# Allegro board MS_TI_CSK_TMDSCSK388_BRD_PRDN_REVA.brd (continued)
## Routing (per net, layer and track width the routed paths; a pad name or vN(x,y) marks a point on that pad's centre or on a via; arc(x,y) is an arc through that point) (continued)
DM388_SPI[0]_SCLK: length 45.9
  L03_SIG1 w0.119: v1(69.57,23.95) 69.89,23.64 71.66,23.64 71.81,23.5 72.96,23.5 73.14,23.31 73.49,23.31 73.88,23.7 v1(75.85,23.7)
  BOTTOM w0.102: R129.2 51.72,8.22 52.74,7.21
  BOTTOM w0.14: 52.74,7.21 53.58,6.37 54.6,6.37 55.2,5.77 63.74,5.77 69.91,11.95 70.17,11.95 75.02,16.79 75.02,18.07 75.85,18.89 75.85,23.19 75.85,23.19 v1(75.85,23.7) ; v1(69.57,23.95) 69.5,23.95 69.27,23.73 J3.68
DM388_TCLK: length 43.6
  TOP w0.102: v1(48.44,10.31) 48.41,10.34 U7.T29
  L03_SIG1 w0.102: v1(48.44,10.31) 48.01,10.74 48.01,13.87 46.94,14.94 46.17,14.94 45.35,15.76 45.35,17.6 45.36,17.6 45.36,17.63 45.62,17.9 47.53,17.9 47.63,18 47.63,19.41 48.04,19.81 48.04,20.25 48.31,20.52 48.31,20.83 48.56,21.08 49.04,21.08 49.43,20.7 49.78,20.7 50.14,21.06 50.14,23.72 51.02,24.59 51.31,24.59 52.25,25.53 52.25,25.99 52.86,26.59
  L03_SIG1 w0.119: v1(53.2,29.95) 53.2,28.87 53.61,28.46 53.61,27.91 53.24,27.54 53.24,26.98 52.86,26.59
  BOTTOM w0.14: v1(53.2,29.95) 53.2,29.94 53.29,29.85 54.7,29.85 54.87,29.67 55.74,29.67 56.32,30.25 57.48,30.25 58.17,30.94 59.34,30.94 59.47,30.81 66.43,30.81 67.35,31.73 J3.38
DM388_TDI: length 38.8
  TOP w0.102: U7.N28 49.11,10.84 v1(49,10.95)
  L03_SIG1 w0.102: 53.79,26.59 53.79,25.97 53.55,25.73 53.44,25.73 52.91,25.2 52.91,24.8 52.29,24.18 51.28,24.18 50.58,23.48 50.58,20.88 49.6,19.91 49.6,19.82 49.08,19.3 48.74,19.3 48.04,18.59 48.04,15.2 48.38,14.86 49.76,14.86 49.97,14.65 49.97,13.96 49.53,13.52 49.53,13.21 49.59,13.15 49.59,11.53 v1(49,10.95)
  L03_SIG1 w0.119: v1(54.21,27.73) 53.79,27.3 53.79,26.59
  BOTTOM w0.14: J3.44 64.01,30.23 63.81,30.42 59.64,30.42 59.13,29.91 56.76,29.91 55.7,28.85 54.75,28.85 54.59,29.01 54.05,29.01 53.87,28.83 53.87,28.07 v1(54.21,27.73)
DM388_TDO: length 68.3
  L06_SIG2 w0.119: v1(76.74,30.99) 77.12,30.61 77.12,30.03 76.87,29.79 76.11,29.79 75.62,30.27 v1(70.47,30.27)
  BOTTOM w0.102: R133.2 47.71,10.41 48.49,9.63 48.49,7.85 48.55,7.79
  BOTTOM w0.14: v1(76.74,30.99) 77.45,30.28 77.45,23.04 77.16,22.75 77.16,18.35 76.33,17.53 76.33,12.75 67.15,3.57 56.66,3.57 56.42,3.33 50.7,3.33 49.5,4.53 49.5,6.32 48.76,7.06 48.76,7.58 48.55,7.79 ; J3.46 68.48,29.73 68.49,29.74 69.93,29.74 v1(70.47,30.27)
DM388_TMS: length 58
  TOP w0.102: U7.T31 49.46,7.86 49.46,7.79
  TOP w0.14: v1(49.46,7.42) 49.46,7.79
  L06_SIG2 w0.119: v1(75.62,31.95) 75.18,31.95 75.04,32.1 69.68,32.1 v1(69.37,32.41)
  BOTTOM w0.14: J3.36 68.74,32.23 68.92,32.41 v1(69.37,32.41) ; v1(49.46,7.42) 51.71,7.42 53.1,6.03 54.46,6.03 55.06,5.43 64.13,5.43 70.3,11.6 70.32,11.6 75.37,16.65 75.37,17.93 76.19,18.75 76.19,23.15 76.27,23.23 76.27,27.75 75.62,28.4 v1(75.62,31.95)
DM388_TPS_SLEEP: length 49.9
  TOP w0.102: v1(49.59,21.08) 49.59,21.06 49.48,20.95 U7.N9 ; U1.F1 33.36,48.06 33.36,47.3 33.18,47.12 v1(33.18,46.74)
  L06_SIG2 w0.102: 56.88,26.59 56.88,26.37 53.69,23.18 52.62,23.18 51.86,22.42 51.86,21.66 51.64,21.44 49.95,21.44 v1(49.59,21.08) ; 33.61,46.3 v1(33.18,46.74)
  L06_SIG2 w0.119: 56.88,26.59 56.88,28.57 56.44,29.01 56.44,31.24 55.63,32.06 55.63,32.61 55.23,33.02 55.23,33.56 55.06,33.72 55.06,33.78 54.29,34.55 54.29,35.32 53.11,36.5 50.82,36.5 50.2,37.13 50.2,40.32 49.91,40.61 49.26,40.61 47.76,42.11 45.93,42.11 44.05,43.99 35.92,43.99 33.61,46.3
DM388_TRSTN: length 39.7
  TOP w0.102: U7.U24 47.15,12.84 47,12.99 47,12.99 v1(46.98,13)
  TOP w0.14: v1(70.38,31.23) 70.87,31.23 70.98,31.34 R120.1
  L06_SIG2 w0.102: v1(46.98,13) 47.37,13.39 47.37,14.66 47.83,15.11 47.83,15.53 48.69,16.38 49.69,16.38 50.19,16.89 54.73,16.89 57.37,19.53
  L06_SIG2 w0.119: v1(70.38,31.23) 69.91,30.76 66.6,30.76 66.3,30.46 63.11,30.46 60.48,27.82 60.48,25.02 59.3,23.84 59.3,21.24 57.59,19.53 57.37,19.53
  BOTTOM w0.14: J3.42 68.48,30.73 68.54,30.79 69.94,30.79 v1(70.38,31.23)
DM388_UART0_CTSN: length 21.2
  TOP w0.102: 57.31,10.29 56.67,10.29 56.44,10.06 56.44,9.34 56.16,9.06 54.76,9.06 U7.D30
  TOP w0.14: 57.31,10.29 59.74,10.29 60.32,10.86 60.32,11.17 60.82,11.67 61.32,11.67 61.44,11.79 65.54,11.79 v1(66.58,12.83)
  BOTTOM w0.14: J5.39 64.72,16.77 64.72,16.77 65.08,16.77 65.09,16.77 65.81,16.77 66.58,16 v1(66.58,12.83)
DM388_UART0_RTSN: length 24.2
  TOP w0.102: 57.31,8 56.71,8 55.94,8.76 54.55,8.76 U7.D31
  TOP w0.14: v1(67.31,12.83) 67.34,12.8 67.34,12.29 66.21,11.16 66.21,9.95 65.71,9.45 64.72,9.45 62.67,7.39 59.6,7.39 59.31,7.68 58.19,7.68 57.87,8 57.31,8
  BOTTOM w0.14: J5.37 64.93,17.27 65.18,17.01 65.91,17.01 66.87,16.05 66.87,13.27 v1(67.31,12.83)
DM388_UART0_RXD: length 61.4
  TOP w0.102: U7.J26 51.48,11.94 50.97,12.44 v1(50.96,12.44)
  L03_SIG1 w0.102: v1(50.96,12.44) 51.27,12.14 51.28,12.14 51.43,11.98 51.43,10.31 50.93,9.81 48.42,9.81 46.73,8.12 46.73,7.79
  L03_SIG1 w0.119: v1(74.48,21.79) 73.43,21.79 72.7,21.06 72.7,18.6 75.82,15.49 75.82,11.07 66.79,2.04 50.94,2.04 50.92,2.05 50.08,2.05 49.65,2.48 49.65,3.18 46.92,5.92 46.92,7.04 46.73,7.22 46.73,7.79
  BOTTOM w0.14: J3.71 73.54,22.73 v1(74.48,21.79)
DM388_UART0_TXD: length 35.8
  TOP w0.14: R80.1 58.56,8.89 58.7,8.74 v1(58.7,8.29)
  L06_SIG2 w0.119: v1(74.15,22.71) 72.57,21.14 69.91,21.14 69.83,21.05 69.8,21.05 67.7,18.95 67.7,17.33 67.83,17.21 71.32,13.72 71.32,10.42 68,7.1 59.9,7.1 v1(58.7,8.29)
  BOTTOM w0.14: J3.69 73.63,23.23 v1(74.15,22.71)
DM388_UART1_RXD: length 41
  TOP w0.102: U7.N26 49.22,11.84 49.12,11.74 49.12,11.69 49.02,11.59 v1(48.98,11.59)
  L03_SIG1 w0.102: 53.25,26.59 52.71,26.05 52.71,24.88 52.21,24.38 51.19,24.38 50.37,23.56 50.37,20.98 49.4,20.01 49.4,19.91 48.99,19.5 48.23,19.5 47.83,19.1 47.83,14.99 48.5,14.32 49.01,14.32 49.37,13.96 49.37,13.65 49.32,13.61 49.32,13.02 49.37,12.97 49.37,12.39 49.37,12.39 49.37,12.08 49.36,12.06 49.36,11.98 v1(48.98,11.59)
  L03_SIG1 w0.119: 53.25,26.59 53.52,26.86 53.52,27.5 53.83,27.81 53.83,30.02 v1(53.24,30.61)
  BOTTOM w0.14: v1(53.24,30.61) 53.56,30.29 54.63,30.29 54.87,30.53 55.7,30.53 56.9,31.73 58.73,31.73 59.14,32.13 61.57,32.13 64.17,34.73 J3.28
DM388_UART1_TXD: length 53.9
  L06_SIG2 w0.119: v1(75.38,36.35) 74.94,36.35 74.9,36.31 73.97,36.31 73.73,36.55 73.73,36.9 73.49,37.14 73.14,37.14 72.35,36.35 67.98,36.35 67.69,36.06 67.69,35.62 67.42,35.35 v1(66.86,35.35)
  BOTTOM w0.14: J3.26 67.01,35.23 66.89,35.35 v1(66.86,35.35) ; R134.1 64.41,6.99 69.77,12.35 70.09,12.35 74.68,16.94 74.68,18.21 75.51,19.04 75.51,23.05 75.42,23.13 75.42,24.1 75.95,24.63 75.95,27.71 75.38,28.29 75.38,30.99 75.21,31.16 75.21,32.86 75.7,33.34 75.7,36.03 v1(75.38,36.35)
DM388_UART2_CTSN: length 8.3
  TOP w0.14: U2.7 v1(49.8,42.44) ; U4.3 v1(54.11,37.34)
  L03_SIG1 w0.119: v1(54.11,37.34) 53.11,38.34 53.11,39.14 v1(49.8,42.44)
DM388_UART2_RTSN: length 12.1
  TOP w0.14: U2.5 48.99,44 48.39,43.41 v1(48.39,42.83) ; U4.6 53.99,38.84 53.99,38.84 v1(54.46,38.84)
  L06_SIG2 w0.119: v1(48.39,42.83) 48.83,42.83 49.03,43.03 49.82,43.03 50.89,41.96 52.33,41.96 54.77,39.52 54.77,39.15 v1(54.46,38.84)
DM388_UART2_RXD: length 91.8
  TOP w0.102: U7.L22 v1(50.48,13.41)
  TOP w0.14: U2.6 49.2,43.5 48.9,43.2 48.9,42.19 v1(49.1,41.99)
  L03_SIG1 w0.102: 57.31,12.07 57.28,12.07 57.26,12.09 54.11,12.09 53.12,13.08 51.24,13.08 50.91,13.41 v1(50.48,13.41)
  L03_SIG1 w0.119: v1(49.1,41.99) 49.1,42.33 49.63,42.86 50.44,42.86 51.55,41.75 54.5,41.75 56.97,44.21 61.31,44.21 61.75,44.65 65.38,44.65 v1(67.01,43.03) ; v1(61.93,11.08) 61.62,10.76 61.39,10.76 61.06,10.43 59.18,10.43 57.54,12.07 57.31,12.07
  L06_SIG2 w0.119: v1(67.01,43.03) 67.38,42.65 67.38,36.15 67,35.76 66.45,35.76 65.98,35.3 65.98,34.07 66.23,33.82 68.02,33.82 68.72,34.53 73.81,34.53 74.03,34.31 74.28,34.31 75.5,33.1 75.93,33.1 77.78,31.25 77.78,25.05 75.86,23.12 73.97,23.12 73.52,22.67 70.73,22.67 70.43,22.97 69.84,22.97 69.75,22.89 68.94,22.89 65.94,19.89 65.94,16.67 66.08,16.54 66.08,14.05 65.1,13.07 63.93,13.07 v1(61.93,11.08)
DM388_UART2_TXD: length 84.1
  TOP w0.14: U2.4 48.82,44.5 v1(48.03,43.71) ; v1(61.14,12.09) 60.69,12.09 60.16,11.56 R79.1
  L03_SIG1 w0.119: v1(75.38,26.25) 77.8,28.68 77.8,34.04 76.23,35.61 76.23,41.36 73.69,43.89 68.22,43.89 67.14,44.97 67.14,48.59 66.54,49.2 64.59,49.2 64.02,48.63 64.02,46.77 62.61,45.37 57.46,45.37 54.11,42.02 51.66,42.02 49.97,43.71 v1(48.03,43.71)
  L06_SIG2 w0.119: v1(61.14,12.09) 61.75,12.09 64.19,14.53 64.19,16.31 64.88,16.99 64.88,18.17 65.17,18.47 65.17,19.74 68.49,23.07 68.75,23.33 68.89,23.46 69.67,23.46 69.8,23.6 72.75,23.6 73.01,23.34 73.8,23.34 74.01,23.55 74.44,23.55 75.69,24.79 75.69,25.94 v1(75.38,26.25)
DM388_USB0_CE: length 6.9
  TOP w0.102: v1(56.98,14.63) 56.49,15.12 55.26,15.12 U7.B20
  BOTTOM w0.102: v1(56.98,14.63) 56.98,14.15 57.31,13.82
  BOTTOM w0.14: 57.31,13.82 57.56,13.56 57.56,12.22 58.04,11.74 59.22,11.74 J5.58
DM388_USB0_DM: length 30.3
  TOP w0.102: U7.B21 55.32,14 62.26,14 63.77,15.51 70.02,15.51 71.86,17.35 71.86,24.59 71.3,25.15 70.74,25.15 v1(70.51,25.38)
  BOTTOM w0.102: J3.62 68.43,25.23 68.57,25.08 70.22,25.08 v1(70.51,25.38)
DM388_USB0_DP: length 30.3
  TOP w0.102: v1(70.51,24.5) 70.16,24.5 70.06,24.6 70.06,24.79 70.2,24.93 71.21,24.93 71.64,24.5 71.64,17.44 69.93,15.72 63.68,15.72 62.17,14.21 55.6,14.21 U7.A21
  BOTTOM w0.102: v1(70.51,24.5) 70.51,24.77 70.41,24.87 68.57,24.87 68.43,24.73 J3.64
DM388_USB0_DRVVBUS: length 33.5
  TOP w0.102: v1(50.51,12.82) 50.51,12.88 50.61,12.98 50.64,12.98 50.98,13.31 U7.K23
  L06_SIG2 w0.102: v1(50.51,12.82) 50.82,13.13 53.86,13.13 54.23,12.75 55.3,12.75 56.03,12.03 57.31,12.03
  L06_SIG2 w0.119: 57.31,12.03 57.63,11.7 61.67,11.7 65.3,15.33 65.3,16.39 65.39,16.49 65.39,19.65 68.84,23.11 69.66,23.11 69.93,23.38 70.35,23.38 70.63,23.09 v1(71.07,23.09)
  BOTTOM w0.14: J3.66 67.82,24.16 69.04,24.16 69.3,24.41 69.73,24.41 70.25,23.88 70.38,23.88 70.75,23.51 70.75,23.41 v1(71.07,23.09)
DM388_USB0_ID: length 24.8
  TOP w0.102: v1(56.37,14.63) 56.2,14.63 55.99,14.84 U7.A20
  L06_SIG2 w0.102: v1(56.37,14.63) 57.19,13.81 57.31,13.81
  L06_SIG2 w0.119: 57.31,13.81 57.47,13.64 62.07,13.64 63.49,15.06 63.49,17.61 64.73,18.85 64.73,19.38 64.73,20.1 68.23,23.6 68.23,24.29 69.44,25.5 v1(69.88,25.5)
  BOTTOM w0.14: J3.60 67.81,25.78 69.73,25.78 69.88,25.63 v1(69.88,25.5)
DM388_USB0_VBUSIN: length 26.5
  TOP w0.102: U7.B22 v1(54.49,13.35)
  L06_SIG2 w0.102: 57.31,15.01 56.15,15.01 v1(54.49,13.35)
  L06_SIG2 w0.119: 57.31,15.01 58.45,13.87 61.91,13.87 63.21,15.17 63.21,17.69 64.51,18.99 64.51,19.29 64.51,20.19 64.64,20.32 67.85,23.53 67.85,24.46 69.19,25.8 69.19,25.91 v1(69.5,26.23)
  BOTTOM w0.14: J3.58 v1(69.5,26.23)
DM388_USB1_CE: length 7
  TOP w0.102: U7.C21 54.48,14.02 v1(54.35,13.89)
  BOTTOM w0.102: v1(54.35,13.89) 56.24,13.89 57.31,12.83 57.31,12.02
  BOTTOM w0.14: J5.60 58.05,11.27 57.31,12.02
DM388_USB1_DM: length 30.7
  TOP w0.102: U7.B23 55.27,13.63 56,13.63 56.14,13.49 62.84,13.49 64.34,14.99 70.49,14.99 72.38,16.88 72.38,22.04 74.51,24.17 74.51,25.27 74.4,25.39 74.24,25.39 74.03,25.19 v1(74.03,25.12)
  BOTTOM w0.102: J3.61 73.06,25.23 73.2,25.37 73.82,25.37 74.03,25.16 v1(74.03,25.12)
DM388_USB1_DP: length 30.7
  TOP w0.102: U7.A23 55.55,13.41 55.91,13.41 56.05,13.27 62.93,13.27 64.43,14.77 70.58,14.77 72.6,16.79 72.6,21.95 74.73,24.08 74.73,25.36 74.49,25.6 74.26,25.6 v1(74.03,25.83)
  BOTTOM w0.102: v1(74.03,25.83) 73.79,25.58 73.2,25.58 73.06,25.73 J3.59
DM388_USB1_DRVVBUS: length 69
  TOP w0.102: U7.AF31 42.98,7.95 43.02,7.91 43.02,7.79
  TOP w0.14: v1(43.49,6.81) 43.02,7.28 43.02,7.79
  L03_SIG1 w0.119: v1(43.49,6.81) 43.49,4.86 45.38,2.97 47.13,2.97 47.71,2.39 47.71,2.39 49.52,0.59 73.22,0.59 78.62,5.98 78.62,23.06 77.19,24.49 76.33,24.49 v1(75.19,25.63)
  BOTTOM w0.14: v1(75.19,25.63) 74.87,25.31 74.87,24.96 74.21,24.3 73.65,24.3 73.48,24.47 73.27,24.47 73.07,24.66 72.56,24.66 J3.63
DM388_USB1_ID: length 30.9
  TOP w0.102: U7.A24 v1(55.92,12.84)
  L06_SIG2 w0.102: v1(55.92,12.84) 56.32,12.45 57.13,12.45 57.31,12.62
  L06_SIG2 w0.119: v1(75.29,24.94) 74.82,24.48 71.12,24.48 70.69,24.92 69.95,24.92 64.95,19.92 64.95,19.84 64.95,18.64 63.76,17.45 63.76,15.02 62.05,13.32 58,13.32 57.31,12.62
  BOTTOM w0.14: v1(75.29,24.94) 74.4,24.05 73.55,24.05 73.38,24.23 J3.65
DM388_USB1_VBUSIN: length 36.8
  TOP w0.102: v1(56.72,12.83) 56.72,12.52 56.61,12.42 55.4,12.42 U7.B24
  L06_SIG2 w0.102: v1(56.72,12.83) 56.33,13.22 54.98,13.22 54.73,12.97 54.33,12.97 54,13.3 54,13.71 53.97,13.74 53.97,14.05 54.53,14.61 55.02,14.61 55.7,15.28 57.31,15.28
  L06_SIG2 w0.119: 57.31,15.28 57.57,15.28 58.68,14.17 61.83,14.17 62.94,15.29 62.94,17.6 62.99,17.65 62.99,17.79 64.29,19.08 64.29,20.29 64.55,20.54 67.42,23.42 67.42,24.79 69.27,26.64 71.74,26.64 71.84,26.54 v1(73.94,26.54)
  BOTTOM w0.14: v1(73.94,26.54) 73.69,26.29 72.56,26.29 J3.57
DM388_VIN[0]A_CLK: length 8.1
  TOP w0.102: U7.C9 54.48,19.96 v1(54.4,19.88)
  BOTTOM w0.102: J5.40 59.21,16.81 58.53,16.81 57.96,17.38 57.96,18.37 58.07,18.48 58.07,19.09 57.64,19.52 57.31,19.52 57.31,19.52 57.04,19.52 56.98,19.58 56.56,20 56.17,20 55.89,20.28 54.8,20.28 v1(54.4,19.88)
DM388_VIN[0]A_D[0]: length 7.6
  TOP w0.102: 57.31,15.55 57.29,15.56 55.26,15.56 U7.B18
  TOP w0.14: v1(60.79,15.41) 59.5,15.41 59.37,15.54 57.31,15.54 57.31,15.55
  BOTTOM w0.102: v1(60.79,15.41) 60.65,15.27 J5.46
DM388_VIN[0]A_D[1]: length 11.2
  TOP w0.102: U7.A17 55.81,16.34 v1(55.95,16.2)
  L03_SIG1 w0.102: v1(55.95,16.2) 56.25,15.89 56.25,15.85 56.41,15.7 57.31,15.7
  L03_SIG1 w0.119: 57.31,15.7 58.86,15.7 60.35,14.2 64.81,14.2 v1(64.88,14.27)
  BOTTOM w0.14: J5.49 v1(64.88,14.27)
DM388_VIN[0]A_D[2]: length 5.6
  TOP w0.102: v1(56.92,16.22) 56.46,16.22 56.04,16.64 55.45,16.64 55.44,16.64 55.27,16.64 U7.B17
  BOTTOM w0.102: 57.31,15.75 57.23,15.82 57.23,15.91 v1(56.92,16.22)
  BOTTOM w0.14: 57.31,15.75 58.03,15.02 58.03,14.77 58.53,14.27 J5.50
DM388_VIN[0]A_D[3]: length 6.4
  TOP w0.102: v1(54.48,15.87) 54.48,15.88 U7.C17
  BOTTOM w0.102: v1(54.48,15.87) 54.91,15.87 55.11,15.67 56.97,15.67 57.31,15.33
  BOTTOM w0.14: 57.31,15.33 57.7,14.94 57.7,14.44 58.37,13.77 J5.52
DM388_VIN[0]A_D[4]: length 7.4
  TOP w0.102: U7.D17 53.98,16.03 v1(53.83,15.88)
  BOTTOM w0.102: v1(53.83,15.88) 54.24,15.47 56.76,15.47 57.31,14.92
  BOTTOM w0.14: J5.54 58.29,13.27 57.4,14.16 57.4,14.83 57.31,14.92
DM388_VIN[0]A_D[5]: length 16.9
  TOP w0.102: U7.F17 52.99,16.33 52.99,15.99 v1(52.96,15.96)
  L03_SIG1 w0.102: v1(52.96,15.96) 53.67,15.24 57.02,15.24 57.19,15.07 57.31,15.07
  L03_SIG1 w0.119: v1(65.6,12.47) 65.6,12.91 65.43,13.07 64.86,13.07 64.66,13.27 64.43,13.27 64.43,13.26 60.2,13.26 58.39,15.07 57.31,15.07
  BOTTOM w0.14: J5.53 64.65,13.27 64.8,13.11 65.4,13.11 65.6,12.92 v1(65.6,12.47)
DM388_VIN[0]A_D[6]: length 17.2
  TOP w0.102: v1(51.29,14.33) 50.99,14.33 U7.L20
  L03_SIG1 w0.102: v1(51.29,14.33) 51.29,14.1 51.46,13.92 53.27,13.92 53.8,14.45 55.43,14.45 56.42,13.46 57.31,13.46
  L03_SIG1 w0.119: v1(64.82,11.27) 63.72,11.27 62.46,12.52 60,12.52 59.06,13.46 57.31,13.46
  BOTTOM w0.14: J5.59 v1(64.82,11.27)
DM388_VIN[0]A_D[7]: length 17.9
  TOP w0.102: v1(51.89,14.35) 51.98,14.44 U7.H20
  L03_SIG1 w0.102: 57.31,13.82 56.49,13.82 55.53,14.78 53.52,14.78 53.09,14.35 v1(51.89,14.35)
  L03_SIG1 w0.119: 57.31,13.82 59.14,13.82 60.1,12.85 62.77,12.85 63.73,11.89 65.08,11.89 v1(65.7,11.27)
  BOTTOM w0.14: v1(65.7,11.27) 65.2,11.77 J5.57
DM388_VIN[0]A_D[8]_BD[0]: length 10.1
  TOP w0.102: v1(56.58,16.66) 56.31,16.66 56.12,16.85 55.37,16.85 55.36,16.84 U7.B16
  L03_SIG1 w0.102: v1(56.58,16.66) 57.01,16.66 57.04,16.64 57.31,16.64
  L03_SIG1 w0.119: v1(61.78,14.75) 61.47,15.06 60.99,15.06 60.74,14.81 60.2,14.81 58.37,16.64 57.31,16.64
  BOTTOM w0.14: v1(61.78,14.75) 62.28,14.75 62.29,14.75 63.27,14.75 63.28,14.77 J5.47
DM388_VIN[0]A_D[9]_BD[1]: length 6.4
  TOP w0.102: U7.C16 54.48,17.22 54.49,17.23 v1(54.49,17.27)
  BOTTOM w0.102: 57.31,16.43 57,16.73 57,16.82 56.55,17.27 v1(54.49,17.27)
  BOTTOM w0.14: 57.31,16.43 58.24,15.49 58.24,15.23 58.7,14.77 J5.48
DM388_VIN[0]A_D[10]_BD[2]: length 13.8
  TOP w0.102: U7.E16 53.06,17.26 v1(53.06,17.29)
  L03_SIG1 w0.102: 57.31,17.08 56.26,17.08 55.65,16.47 53.45,16.47 53.06,16.86 v1(53.06,17.29)
  L03_SIG1 w0.119: 57.31,17.08 61.38,17.08 61.64,16.81 61.64,15.68 v1(62.06,15.27)
  BOTTOM w0.14: v1(62.06,15.27) J5.45
DM388_VIN[0]A_D[12]_BD[4]: length 16.9
  TOP w0.102: U7.J16 51.58,16.84 51.73,16.99 v1(51.73,17.29)
  L03_SIG1 w0.102: 57.31,15.34 57.21,15.34 57.11,15.44 55.55,15.44 54.73,16.26 53.19,16.26 52.78,16.68 51.86,16.68 51.73,16.8 v1(51.73,17.29)
  L03_SIG1 w0.119: v1(65.02,13.54) 64.71,13.85 60.22,13.85 58.73,15.34 57.31,15.34
  BOTTOM w0.14: J5.51 64.75,13.77 64.98,13.54 v1(65.02,13.54)
DM388_VIN[0]A_DE: length 8.8
  TOP w0.102: U7.C12 54.48,19.23 v1(54.4,19.31)
  BOTTOM w0.102: J5.42 58.53,16.27 57.58,17.22 57.58,18.34 57.82,18.58 57.82,18.98 57.54,19.27 57.01,19.27 56.47,19.8 56.09,19.8 55.81,20.08 54.89,20.08 54.79,19.98 54.79,19.7 v1(54.4,19.31)
DM388_VIN[0]A_FLD: length 13.9
  TOP w0.102: v1(51.48,18.76) 51.48,18.76 U7.J13
  BOTTOM w0.102: J5.26 58.3,20.77 57.38,21.69 57.38,23.28 56.99,23.67 53.93,23.67 53.42,23.16 53.42,22.72 52.89,22.2 52.7,22.2 52.37,21.88 52.37,21.11 52.33,21.07 51.48,20.22 51.48,19.2 51.48,19.2 v1(51.48,18.76)
DM388_VIN[0]A_HSYNC: length 12.6
  TOP w0.102: U7.D13 53.98,18 v1(53.83,17.85)
  L03_SIG1 w0.102: v1(53.83,17.85) 53.47,17.49 53.47,17.04 53.84,16.67 55.56,16.67 56.24,17.35 57.31,17.35
  L03_SIG1 w0.119: v1(61.09,19.76) 60.15,18.82 58.77,18.82 57.31,17.35
  BOTTOM w0.14: v1(61.09,19.76) 60.6,19.27 J5.32
DM388_VIN[0]A_VSYNC: length 12
  TOP w0.102: v1(54.48,17.83) 54.48,17.83 U7.C13
  L03_SIG1 w0.102: 57.31,19.3 57.15,19.3 55.68,17.83 v1(54.48,17.83)
  L03_SIG1 w0.119: 57.31,19.3 59.58,19.3 v1(61.09,20.8)
  BOTTOM w0.14: J5.19 62.53,22.27 62.41,22.15 62.41,21.92 61.84,21.35 61.64,21.35 v1(61.09,20.8)
DM388_VIN[0]B_CLK: length 9.4
  TOP w0.102: v1(52.1,19.32) 52.1,19.24 51.98,19.12 U7.H12
  BOTTOM w0.102: v1(52.1,19.32) 52.1,18.88 52.67,18.31 53.4,18.31 53.42,18.3 54.79,18.3 55.51,17.58 56.62,17.58 57.31,16.89
  BOTTOM w0.14: J5.44 58.43,15.77 57.31,16.89
DM388_WARM_RSTN: length 59
  TOP w0.102: v1(42.26,10.88) 42.08,10.7 42.08,10.44 U7.AH29
  L06_SIG2 w0.102: 57.31,17.89 56.4,17.89 54.89,16.38 50.97,16.38 50.45,15.86 50.45,15.73 49.66,14.94 48.51,14.94 47.78,14.21 47.78,12.85 47.41,12.48 47.41,9.66 49.19,7.87 49.56,7.87 49.64,7.79 ; 46.33,7.79 46.33,8.05 46.03,8.35 43.92,8.35 41.95,10.33 41.95,10.57 v1(42.26,10.88)
  L06_SIG2 w0.119: 57.31,17.89 60.06,20.65 60.06,23.32 62.92,26.18 62.92,28.02 63.82,28.91 69.05,28.91 v1(69.36,29.23) ; 49.64,7.79 50.61,6.82 50.61,5.93 50.39,5.71 47.92,5.71 46.99,6.64 46.99,7.13 46.33,7.79
  BOTTOM w0.102: 40.31,7.79 40.31,8.15 40.42,8.26 41.36,8.26 41.43,8.33 41.43,9.73 41.95,10.25 41.95,10.57 v1(42.26,10.88)
  BOTTOM w0.14: J3.48 v1(69.36,29.23) ; 40.31,7.79 R131.2
DM388_WLAN_CLKOUT: length 2.8
  TOP w0.14: R37.2 64.32,37.67 63.49,36.84 U5.7
DM388_WLAN_CLKOUT1: length 33
  TOP w0.14: R37.1 66.05,38.86 65.69,39.22 64.47,39.22 64.12,38.87 64.12,38.54 63.92,38.34 63.92,37.88 63.66,37.62 63.3,37.62 63.18,37.75 58.17,37.75 58.11,37.69 58.09,37.69 57.84,37.44 57.84,37.43 56.82,36.4 56.82,33.63 v1(58.08,32.37)
  L06_SIG2 w0.102: 57.12,26.23 56.29,25.4 56.29,23.63 55.13,22.47 53.27,22.47 v1(52.94,22.79)
  L06_SIG2 w0.119: 57.12,26.23 57.39,26.5 57.39,28 58.08,28.69 v1(58.08,32.37)
  BOTTOM w0.102: v1(52.94,22.79) 52.63,22.49 52.63,22.48 52.12,21.97 52.12,21.15 51.98,21.01 R116.1
DM388_WLAN_EN: length 43.2
  TOP w0.102: 52.33,26.69 52.33,25.87 51.31,24.85 50.78,24.85 50.27,24.35 50.27,24.03 50.08,23.84 U7.M2
  TOP w0.14: 52.33,26.69 52.33,28.26 53.12,29.05 53.48,29.05 54.61,30.18 54.61,32.73 54.38,32.96 54.38,35.43 55.84,36.89 55.84,37.83 56.26,38.25 56.26,40.74 54.89,42.11 53.64,42.11 v1(53.32,42.43)
  L03_SIG1 w0.119: v1(53.32,42.43) 52.07,43.68 52.07,48.56 51.91,48.72 51.91,49.33 51.34,49.91 49.43,49.91 44.91,54.43 v1(43.84,54.43)
  BOTTOM w0.14: v1(43.84,54.43) 44.24,54.82 U12.5
DM388_WLAN_IRQ: length 45.4
  TOP w0.102: U7.M3 49.53,23.34 v1(49.5,23.37)
  L03_SIG1 w0.119: v1(42.58,55.9) 42.58,54.17 44.43,52.32 44.43,51.36 47.34,48.45 47.34,42.78 49.43,40.69 50.67,40.69 52.59,38.77 52.59,36.06 v1(52.91,35.75)
  L06_SIG2 w0.102: 56.34,26.59 56.34,26.47 53.46,23.58 51.65,23.58 51.56,23.67 49.8,23.67 v1(49.5,23.37)
  L06_SIG2 w0.119: v1(52.91,35.75) 53.32,35.34 53.32,34.59 54.57,33.34 54.57,32.47 54.54,32.43 54.54,31.88 54.57,31.85 54.57,31.81 55,31.38 55.27,31.38 55.88,30.76 55.88,28.78 56.34,28.32 56.34,26.59
  BOTTOM w0.14: U12.7 v1(42.58,55.9)
EN_LS_3V3: length 49.4
  TOP w0.102: U1.L4 v1(36.39,49.82)
  TOP w0.254: R9.2 v1(42.59,51.2)
  L06_SIG2 w0.203: v1(42.59,51.2) 40.75,49.35 37.27,49.35 36.81,49.82 v1(36.39,49.82) 36.05,50.16 35.42,50.16 35.16,49.89 34.19,49.89 31.52,47.23 26.21,47.23 25.19,48.25 16.03,48.25 9.07,41.29 v1(9.07,35.05)
  BOTTOM w0.14: J4.68 11.21,34.89 10.7,34.89 10.67,34.93 10.66,34.93 10.52,35.07 10.52,35.54 10.37,35.69 9.71,35.69 v1(9.07,35.05)
EN_TPS51216: length 25
  TOP w0.102: U1.L5 v1(36.39,50.47)
  L03_SIG1 w0.102: 34.61,46.3 34.61,47.81 35.7,48.91 36.41,48.91 36.58,48.74 37.04,48.74 37.21,48.92 37.21,49.43 36.86,49.78 36.86,49.99 v1(36.39,50.47)
  L03_SIG1 w0.119: 34.61,46.3 34.61,39.79 v1(28.22,33.4)
  BOTTOM w0.14: U14.16 27.79,33.12 28.07,33.4 v1(28.22,33.4) 28.25,33.38 28.25,32.95 28.02,32.72 U14.17
ENET_RSTN: length 49.6
  TOP w0.102: v1(53.39,26.11) 52.86,26.11 51.4,24.65 50.87,24.65 50.48,24.26 U7.L2
  L06_SIG2 w0.102: 44.34,26.59 44.48,26.45 49.45,26.45 50.47,25.43 51.27,25.43 51.95,26.11 v1(53.39,26.11)
  L06_SIG2 w0.119: v1(22.1,37.75) 22.54,37.75 22.78,37.98 31.77,37.98 32.49,37.26 33.87,37.26 35.21,35.92 37.37,35.92 38.78,34.51 41.32,34.51 41.33,34.49 41.65,34.49 43.61,32.54 43.61,31.5 43.77,31.34 43.77,27.16 44.34,26.59
  BOTTOM w0.14: v1(22.1,37.75) 21.65,37.75 20.57,38.83 17.71,38.83 17.7,38.83 J4.81
HDDAC_A: length 5.9
  TOP w0.102: 57.31,20.76 56.96,20.41 55.55,20.41 U7.A9
  TOP w0.14: v1(57.42,20.96) 57.42,20.87 57.31,20.76
  BOTTOM w0.102: v1(57.42,20.96) 57.85,20.54 58.06,20.54 58.33,20.27 J5.28
  BOTTOM w0.14: R112.2 56.76,22.14 57.11,21.79 57.11,21.47 57.11,21.47 57.11,21.28 v1(57.42,20.96)
HDDAC_B: length 6.4
  TOP w0.102: U7.A8 55.86,20.84 55.91,20.79 v1(56.8,20.79)
  BOTTOM w0.102: J5.30 58.47,19.77 57.96,20.28 57.63,20.28 57.62,20.29 57.31,20.29 v1(56.8,20.79) 56.33,20.79 55.58,21.54 R113.2
HDDAC_C: length 31.4
  TOP w0.102: U7.B8 55.26,21.12 56.35,21.12 56.35,21.12 56.62,21.12 57.31,21.81 57.31,22.02
  TOP w0.14: 57.31,22.02 57.9,22.61 57.9,24.86 58.21,25.16 58.21,26.56 57.84,26.92 57.84,27.43 58.6,28.2 59.67,28.2 60.14,28.67 R64.2 62.93,28.67 63.2,28.39 63.2,28.39 v1(63.52,28.07)
  L03_SIG1 w0.119: v1(63.52,28.07) 63.52,26.76 61.07,24.3 61.07,21.74 62.09,20.72 62.09,16.88 62.5,16.48 v1(62.5,15.67)
  BOTTOM w0.14: v1(62.5,15.67) 62.45,15.72 62.45,16.17 62.55,16.27 J5.41
HDDAC_HSYNC: length 9
  TOP w0.102: v1(53.19,19.88) 53.48,20.17 U7.E9
  BOTTOM w0.102: v1(53.19,19.88) 54,20.69 56.14,20.69 56.42,20.41 56.82,20.41 57.2,20.03 57.52,20.03 57.52,20.03 57.85,20.03 58.55,19.33 58.55,19 58.55,18.99 58.54,18.98 58.54,17.98 58.75,17.77 J5.36
HDDAC_VREF: length 13.1
  TOP w0.102: v1(56.46,21.5) 56.03,21.5 55.86,21.34 U7.B7
  TOP w0.178: R68.2 62.15,26.04 61.87,26.32 v1(61.32,26.32)
  TOP w0.254: v1(61.32,26.32) 61.29,26.32 61.22,26.39 60.4,26.39 R66.2
  TOP w0.381: R66.2 C46.2
  L05_PWR2 w0.381: v1(56.46,21.5) 57.05,22.1 58.83,22.1 61.32,24.59 v1(61.32,26.32)
HDDAC_VSYNC: length 8.7
  TOP w0.102: v1(53.76,19.88) 53.98,20.09 U7.D9
  BOTTOM w0.102: v1(53.76,19.88) 54.37,20.49 56.06,20.49 56.34,20.21 56.68,20.21 57.11,19.78 57.41,19.78 57.42,19.77 57.75,19.77 58.33,19.19 58.33,18.31 58.24,18.23 58.24,17.58 58.55,17.27 J5.38
NRESPWRON2: length 107.5
  TOP w0.102: 29.42,54.4 30.44,53.39 30.44,52.5 30.62,52.32 31.06,52.32 U1.C7
  TOP w0.14: U11.1 41.42,1.13 41.3,1.02 v1(40.03,1.02) ; v1(27.23,56.28) R7.2 28.1,55.73 29.42,54.4
  L03_SIG1 w0.119: v1(8.13,27.53) 7.78,27.18 7.78,18.01 8.79,17 8.79,10.15 18.15,0.79 38.01,0.79 38.65,1.43 39.62,1.43 v1(40.03,1.02)
  L06_SIG2 w0.119: v1(27.23,56.28) 27.23,54.88 26.7,54.36 24.39,54.36 21.37,51.33 14.71,51.33 14.07,50.69 10.05,50.69 8.03,48.67 8.03,31.29 7.51,30.78 7.51,28.15 v1(8.13,27.53)
OSC_WAKE: length 59
  TOP w0.102: v1(47.03,10.96) 47.14,10.84 U7.U28
  L03_SIG1 w0.102: 44.81,7.79 44.81,8.46 45.69,9.35 46.63,9.35 47.4,10.12 47.4,10.58 v1(47.03,10.96)
  L03_SIG1 w0.119: v1(74.34,21.1) 74.03,20.79 74.03,18.88 76.39,16.51 76.63,16.27 76.63,10.35 67.5,1.21 49.66,1.21 48.84,2.03 48.84,2.77 45.23,6.38 44.81,6.8 44.81,7.79
  BOTTOM w0.14: J3.73 73.21,22.23 v1(74.34,21.1)
PLL_1V8: length 125.5
  TOP w0.102: U7.L13 50.48,18.38 50.94,18.84 v1(50.94,18.88) ; v1(50.95,15.83) 50.48,15.35 U7.L19 ; v1(48.41,13.08) 48.15,13.34 U7.T23 ; U7.AA19 45.05,15.34 v1(45.01,15.38)
  TOP w0.152: U7.V9 46.98,19.9 v1(46.95,19.88) 46.48,19.4 U7.W11
  TOP w0.381: v1(29.87,56.01) 29.6,56.28 C8.1 29.11,55.51 29.99,54.63 29.99,54.37 31,53.36 31,53.02 U1.C8
  L03_SIG1 w0.203: v1(50.95,15.83) 50.95,16.51 50.48,16.99 50.48,18.43 v1(50.94,18.88)
  L03_SIG1 w0.254: v1(45.01,15.38) 44.5,15.89 44.5,17 45.01,17.51 45.01,17.75 45.68,18.41 46.69,18.41 46.97,18.69 46.97,19.07 46.95,19.08 v1(46.95,19.88)
  L05_PWR2 w0.305: 46.3,23.36 46.8,23.85 55.71,23.85 56.67,24.81 56.67,25.91 57.43,26.67 57.43,27.71 57.94,28.22 57.94,31.37 59.02,32.45 59.02,32.8 59.03,32.81 59.03,33.45 57.53,34.95 57.53,46 56.45,47.09 50.8,47.09 49.18,45.47 43.46,45.47 42.19,44.2 40.98,44.2 40.52,44.66 40.52,46.72 42.12,48.31 45.01,48.31 46.33,49.63 46.33,51.1 46.8,51.56 46.8,53.82 43.74,56.87 30.74,56.87 v1(29.87,56.01)
  L05_PWR2 w0.33: v1(46.95,19.88) 46.95,20.12 46.3,20.77 46.3,21.06
  L05_PWR2 w0.381: 46.3,23.36 46.3,21.06 ; v1(48.41,13.08) 48.25,13.08 47.88,13.45 47.88,13.69 ; 47.88,13.69 46.76,14.82 46.68,14.82 46.64,14.86 46.63,14.86 46.17,14.86 45.66,15.38 v1(45.01,15.38) ; 47.88,13.69 47.88,14.23 48.26,14.61 49.02,14.61 49.68,15.27 50.39,15.27 v1(50.95,15.83)
  BOTTOM w0.102: v1(45.01,15.38) 44.91,15.47 44.17,15.47 43.92,15.22 41.57,15.22
  BOTTOM w0.178: 41.57,15.22 C149.2
  BOTTOM w0.203: v1(50.95,15.83) 50.93,15.81 C152.1 ; v1(50.94,18.88) 50.71,18.88 50.42,18.59 C119.1 ; v1(48.41,13.08) 48.38,13.11 47.96,13.11 C171.1 ; C139.2 45.19,15.56 45.01,15.38 v1(45.01,15.38)
  BOTTOM w0.254: v1(46.95,19.88) 46.87,19.97 C160.2
PMIC_3V3: length 13.8
  TOP w0.203: 38.06,54.09 U1.L8 U1.L7 ; C31.1 32.51,44.51 32.7,44.69 U1.E1
  TOP w0.254: U1.G2 U1.G1 34,45.75 33.76,45.52 ; U1.F3 U1.F2 U1.E1
  TOP w0.33: v2(38.48,50.68) U1.N5
  BOTTOM w0.254: v2(38.48,50.68) 38.64,50.68 38.68,50.71 C74.1
  vias: v1(13.36,37.85) v1(13.36,37.21) v1(14.13,37.85) v1(14.13,37.21) v1(14.89,37.85) v1(14.89,37.21) v1(32.35,42.6) v1(32.35,41.97) v1(32.35,41.33) v1(32.98,42.6) v1(32.98,41.97) v1(32.98,41.33) v1(40.42,55.5) v1(40.42,54.86) v1(40.42,54.23) v1(41.05,55.5) v1(41.05,54.86) v1(41.05,54.23)
REFGND: length 2.9
  TOP w0.102: U1.G7 v1(34.21,52.19)
  TOP w0.381: C10.1 v1(31.78,55.75) ; C11.1 35.21,55.75 v1(35.72,56.26) ; R6.2 v1(34.88,59.51)
  BOTTOM w0.254: C71.1 33.91,51.89 v1(34.21,52.19)
RF_ANT1: length 1.9
  TOP w0.406: 54.15,62.64 MOD1.32
  TOP w0.635: 54.15,62.64 54.15,63.07 arc(54.02,63.37) 53.73,63.49 R4.1
RF_ANT2: length 2.1
  TOP w0.406: 63.95,62.62 MOD1.18
  TOP w0.635: R5.1 arc(64.2,63.24) 63.95,62.62
TPS_CORE_CVDD: length 13.7
  BOTTOM w0.305: C190.1 27.84,52.2 25.56,54.48 21.75,54.48 20.22,56.01 20.22,58.09 v1(19.51,58.8)
  vias: v1(15.65,57.25) v1(15.65,56.49) v1(15.65,55.73) v1(15.65,54.97) v1(16.26,57.63) v1(16.26,56.87) v1(16.26,56.11) v1(16.26,55.35) v1(16.82,58.83) v1(17.73,58.8) v1(18.62,58.8) v1(19.08,46.36) v1(19.08,45.72) v1(19.08,45.09) v1(19.84,46.46) v1(20.45,46.46) v1(21.16,46.43) v1(21.49,45.72) v1(21.49,45.09)
TPS_CVDD_ARM: length 14.1
  TOP w0.102: U1.D4 v1(32.26,50.24)
  L03_SIG1 w0.178: v1(23.4,46.48) 24.54,46.48 26.06,48.01 26.06,50.04 26.95,50.93 29.59,50.93 30.76,49.75 31.77,49.75 v1(32.26,50.24)
  L03_SIG1 w0.381: v1(23.4,46.48) 23.4,45.59 v1(23.65,45.34)
TPS_CVDD_HDVICP: length 8.6
  TOP w0.102: U1.K2 v1(36.16,48.52)
  L03_SIG1 w0.178: v1(39.35,42.62) 39.35,43.64 38.51,44.48 37.75,44.48 35.39,46.84 35.39,47.75 v1(36.16,48.52)
TPS_GPIO_3V3: length 19.5
  TOP w0.102: v1(31.98,54.26) 32.35,53.88 32.35,52.77 32.38,52.74 32.38,52.29 U1.E7
  TOP w0.381: R9.1 v1(43.57,52.54)
  L06_SIG2 w0.178: v1(31.98,54.26) 32.42,53.82 34.33,53.82 35.32,52.83 35.32,51.28 35.58,51.02 35.97,51.02 35.98,51.02 35.99,51.02 36.49,51.52 39.87,51.52 41.64,53.3 43.28,53.3 43.57,53.01 v1(43.57,52.54)
  BOTTOM w0.254: C70.1 32.47,53.77 v1(31.98,54.26)
TPS_HDMI_CSI_1V8: length 77.1
  TOP w0.152: v1(46,19.82) 46.02,19.84 U7.W10
  TOP w0.254: 38.26,50.03 U1.N4 ; U7.K14 v1(50.98,18.3)
  TOP w0.381: 38.26,50.03 38.26,50.03 39.14,50.03 40.03,50.93 v1(40.16,50.93) 40.54,50.93 40.8,50.67 C21.1
  L05_PWR2 w0.254: v1(46,19.82) 45.24,19.82 44.1,20.96
  L05_PWR2 w0.381: v1(46,19.82) 46.42,19.4 46.7,19.4 46.74,19.36 46.98,19.36 47.85,18.5 47.85,18.2 48.37,17.67 49.04,17.67 49.19,17.82 49.23,17.82 49.65,18.24 50.35,18.24 50.41,18.3 v1(50.98,18.3)
  L05_PWR2 w0.508: v1(40.16,50.93) 41.3,49.78 41.3,48.39 39.86,46.94 39.86,44.93 39.86,44.93 39.86,44.38 40.71,43.54 43.29,43.54 44.56,44.81 49.53,44.81 51.15,46.42 55.97,46.42 56.77,45.62 56.77,33.76 57.13,33.4 57.13,31.78 56.24,30.89 56.24,27.04 53.56,24.36 45.2,24.36 44.1,23.26 44.1,20.96
  BOTTOM w0.203: v1(50.98,18.3) 51.56,18.3 51.61,18.25 51.62,18.25 C123.1 ; v1(46,19.82) 45.19,19.82 44.63,20.37 C110.2
TPS_INT1: length 215.8
  TOP w0.102: 41.85,7.79 41.85,7.95 41.98,8.08 U7.AH31 ; U1.L3 v1(36.81,49.17)
  TOP w0.14: 41.85,7.79 41.85,6.49 41.84,6.48 41.84,5.91 41.84,5.91 41.84,5.88 40.76,4.8 40.68,4.8 40.41,4.53 40.41,3.81 40.54,3.68 40.54,2 40.23,1.68 40.1,1.68 39.81,1.4 39.2,1.4 v1(38.82,1.02) ; v1(42.83,50.53) 43.19,50.17 TP8.1
  L03_SIG1 w0.102: v1(36.81,49.17) 35.43,49.17 35.01,48.74 33.03,48.74 30.58,46.3
  L03_SIG1 w0.119: v1(75.23,33.96) 75.23,33.19 73.93,31.88 70.48,31.88 69.99,31.39 69.99,31.06 70.06,31 70.06,30 70.22,29.84 70.66,29.84 71.08,30.26 71.47,30.26 71.83,29.9 71.83,28.78 71.33,28.28 68.66,28.28 68.46,28.48 68.46,29.74 66.37,31.83 65.22,31.83 64.92,31.53 64.92,30.8 64.72,30.6 60.93,30.6 58.91,28.58 58.91,27.81 v1(58.36,27.27) ; v1(38.82,1.02) 38.37,0.57 17.99,0.57 17.69,0.86 8.52,10.04 8.52,16.66 7.5,17.68 7.5,31.01 8.47,31.99 8.47,35.65 9.4,36.59 15.26,36.59 17.32,38.64 22.92,38.64 30.58,46.3
  L06_SIG2 w0.102: v1(36.81,49.17) 37.36,48.62 38.71,48.62 39.17,48.16 39.55,48.16
  L06_SIG2 w0.119: v1(42.83,50.53) 41.91,49.61 41.91,49.2 40.87,48.16 39.55,48.16 ; v1(38.82,1.02) 41.24,3.44 55.48,3.44 56.14,2.78 58.15,2.78 59.64,4.27 65.8,4.27 71.76,10.23 71.76,13.9 68.14,17.52 68.14,18.74 69.57,20.16 69.57,20.19 69.81,20.43 69.84,20.43 70.05,20.65 70.16,20.65 70.2,20.69 73.47,20.69 73.92,21.15 73.92,21.79 74.34,22.21 75.26,22.21 78,24.95 78,31.63 75.67,33.96 v1(75.23,33.96)
  BOTTOM w0.14: J5.2 v1(58.36,27.27)
TPS_LDO5_3V3: length 1.4
  TOP w0.203: U1.K1 v2(35.95,47.5)
  BOTTOM w0.254: C76.1 35.42,47.96 35.88,47.5 v2(35.95,47.5)
TPS_LDO6_3V3: length 8.4
  TOP w0.127: 37.57,47.8 37.57,48.4 38.36,48.4
  TOP w0.152: 37.57,47.8 38.13,47.24 38.74,47.24 38.84,47.35 38.84,47.92 38.36,48.4
  TOP w0.254: 37.57,48.4 U1.M2
  TOP w0.381: 38.84,47.35 38.98,47.35 40.19,46.13 41.11,46.13 41.34,45.91 C26.1
TPS_USB_1V8: length 79.1
  TOP w0.102: U7.K19 51.07,15.34 51.53,15.79 v1(51.53,15.87)
  TOP w0.254: v1(51.53,15.87) 51.48,15.92 U7.J17
  TOP w0.305: 38.1,46.6 37.24,47.46 37.24,47.94 37.25,47.94 U1.M1
  TOP w0.381: 38.1,46.6 38.68,46.6 39.98,45.29 40.68,45.29 v1(41.08,44.89) C29.1
  L05_PWR2 w0.305: 43.91,46.8 43.46,46.36 42.55,46.36 v1(41.08,44.89) ; 50.83,48.26 54.64,48.26 55.15,47.75 60.96,47.75 63.53,45.19 63.53,38.85 62.82,38.13 62.82,36.6 64.16,35.26 64.16,30.59 63.04,29.46 63.04,27.87 63.28,27.63 63.28,15.49 61.93,14.15 59.67,14.15 58.2,15.62 55.53,15.62 54.6,14.7 52.35,14.7 51.53,15.52 v1(51.53,15.87)
  L05_PWR2 w0.381: 43.91,46.8 49.37,46.8 50.83,48.26
  BOTTOM w0.102: 51.49,15.83 v1(51.53,15.87)
  BOTTOM w0.178: C148.1 51.49,15.83
  BOTTOM w0.203: v1(51.53,15.87) 51.57,15.91 51.57,16.33 51.59,16.36 C136.2
TPS_USB_3V3: length 66.2
  TOP w0.127: 38.46,49.05 37.57,49.05 U1.M3
  TOP w0.152: v1(50.45,14.3) 50.45,14.37 U7.M20
  TOP w0.203: 38.46,49.05 39.5,48.01 39.87,48.01
  TOP w0.254: U7.M19 U7.M20
  TOP w0.381: v2(42.35,47.8) 41.75,47.8 41.55,48.01 39.87,48.01
  L04_PWR1 w0.305: v1(50.45,14.3) 51.08,13.67 53.04,13.67 53.6,14.22
  L04_PWR1 w0.381: v2(42.35,47.8) 43.92,47.8 44.99,46.74 52.14,46.74 55.29,43.59 56.14,43.59 60.23,39.5 60.23,38.65 62.78,36.09 62.78,33.31 60.99,31.53 60.99,28.83 60.23,28.07 60.23,26.54 60.56,26.21 60.56,20.57 57.49,17.5 56.52,17.5 55.43,16.41 55.43,16.06 53.6,14.22
  BOTTOM w0.203: C167.2 51.01,13.79 50.5,14.3 v1(50.45,14.3)
  BOTTOM w0.254: C172.1 51.22,13.78 C167.2
  BOTTOM w0.381: C79.1 44.05,47.86 43,47.86 42.94,47.8 v2(42.35,47.8)
TPS_VDAC_1V8: length 6.3
  TOP w0.203: C18.1 39.33,51.75 38.91,51.33 U1.N6
  TOP w0.381: TP7.1 41.81,53.59 40.8,53.59 40.2,53 R8.1 C18.1
TPS_VDDA_1V8: length 126.8
  TOP w0.127: 34.85,54.4 34.83,54.38 34.83,52.78 34.67,52.63 U1.H8 34.65,53.72 34.65,53.72
  TOP w0.152: U7.M28 U7.N27 U7.M26 U7.M25
  TOP w0.254: MOD1.38 C5.1 ; v1(62.96,38.95) 62.96,39.08 63.23,39.35 C36.1 63.63,39.93 63.67,39.97 U3.2 ; U7.T10 48.39,19.84 v1(48.43,19.88) 48.48,19.92 U7.R9 U7.T9 U7.T10 ; U7.T10 47.54,19.84 v1(47.52,19.86) ; U7.N22 49.44,13.8 v1(48.99,13.8) ; v1(48.99,13.8) 48.98,13.81 U7.P21 U7.P20 ; v1(48.99,13.8) 48.99,13.35 U7.P23 ; v1(52.93,47.57) 52.87,47.63 C24.1 52.3,47.12 52.28,47.1 U2.16 ; U5.16 61.01,31.85 60.99,31.82 C44.1 60.31,31.31 59.5,32.12 59.5,32.68 v1(59.59,32.77) ; v1(48.99,12.23) 49.1,12.34 U7.N25 U7.M25
  TOP w0.381: v2(35.16,54.89) 34.85,54.59 34.85,54.4 ; C5.1 51.26,57.6 v1(50.92,57.27) ; v1(39.4,59.94) 39.33,59.88 C3.1 ; C4.1 40.6,59.89 v1(40.54,59.94) ; R14.1 v1(63.46,47.38)
  L03_SIG1 w0.381: v2(35.16,54.89) 35.75,55.49 36.14,55.49 37.2,56.54 37.2,60.2 37.58,60.58 v1(39.4,60.58) v1(40.54,60.58) ; v1(63.46,47.38) 62.89,47.38 62.67,47.6 60.99,47.6 v1(60.58,47.19) v1(59.77,47.19) 59.44,47.19 59.06,47.57 v1(52.93,47.57) ; v1(47.8,58.95) 49.21,60.35 49.66,60.35 v1(50.07,60.76) 50.07,59.93 50.52,59.48 50.52,57.67 v1(50.92,57.27)
  L05_PWR2 w0.381: 52.1,12.19 52.1,8.64 50.78,7.32 50.78,5.84 49.36,4.43 42.26,4.43 41.81,4.88 40.61,4.88 39.8,4.07 21.1,4.07 12.35,12.83 12.35,21.81 v1(13.36,22.83)
  L06_SIG2 w0.254: v1(59.77,47.19) v1(60.58,47.19) 60.94,47.55 62.78,47.55 62.95,47.38 v1(63.46,47.38)
  BOTTOM w0.178: C159.1 49.03,13.84 v1(48.99,13.8) ; v1(47.8,58.95) 47.86,58.89 C68.1 47.84,58.37 U12.16
  BOTTOM w0.203: v1(48.43,19.88) 48.54,19.77 C115.1 C116.1 47.91,19.36 C117.1 47.32,19.56 47.52,19.75 v1(47.52,19.86) ; C157.1 C156.1 48.94,13.8 v1(48.99,13.8)
  BOTTOM w0.254: J4.24 v1(13.36,22.83) ; R117.2 55.71,19.65 55.93,19.43 56.15,19.43 v1(56.21,19.37)
  BOTTOM w0.381: R86.1 v1(50.07,60.76)
TPS_VHD_1V1: length 29.8
  TOP w0.254: v1(50.94,17.27) 50.98,17.23 U7.K16
  TOP w0.381: TP15.1 67.09,10.11 U9.5 67.09,8.69 66.73,8.34 C58.1 65.1,8.34 63.34,6.57 v1(63.34,6.23)
  L04_PWR1 w0.381: v1(61.14,14.66) 61.14,14.09 61.22,14.01 61.22,13.99 63.34,11.87 v1(63.34,6.23)
  L05_PWR2 w0.381: v1(50.94,17.27) 50.99,17.22 50.99,17.03 51.37,16.65 54.84,16.65 55.47,17.27 57.52,17.27 60.14,14.66 v1(61.14,14.66)
  BOTTOM w0.203: C130.1 50.98,17.23 v1(50.94,17.27)
TV_OUT0: length 23.4
  TOP w0.102: 58.17,21.87 58.17,21.17 57.21,20.21 55.74,20.21 55.59,20.06 55.26,20.06 U7.B9
  TOP w0.14: v1(61.5,23.22) 61.18,22.9 61.18,22.75 61.07,22.63 60.3,22.63 59.72,22.06 R74.1 58.36,22.06 58.17,21.87
  L06_SIG2 w0.119: v1(61.5,23.22) 61.5,23.82 62.09,24.41 63.67,24.41 64.5,25.24 65.94,25.24 66.78,25.24 69.26,27.73 v1(73.39,27.73)
  BOTTOM w0.14: J3.53 v1(73.39,27.73)
VBACKUP: length 90.2
  TOP w0.203: v1(32.26,51.77) U1.D7
  L04_PWR1 w0.381: v1(32.26,51.77) 32.26,53.18 33.56,54.48 33.56,55.63 34.84,56.91 47.26,56.91 47.91,56.26 51.97,56.26 53.24,54.99 53.24,50.67 53.88,50.04 64.7,50.04 65.56,49.18 65.56,48.51 66.36,47.71 66.36,47.18 66.18,47 66.18,45.86 68.04,44 70.35,44 71.79,42.56 71.79,41.81 72.67,40.92 72.67,17.65 71.25,16.23 v1(65.69,16.23)
  BOTTOM w0.14: J5.43 65.22,15.77 v1(65.69,16.23)
  BOTTOM w0.254: v1(32.26,51.77) 31.75,51.77 31.65,51.66 31.31,51.66 C72.1
VDAC_1V8: length 58.5
  TOP w0.254: U7.J14 51.88,17.84 51.91,17.8 v1(51.95,17.8) ; v1(50.01,17.34) U7.L15 U7.L14
  TOP w0.381: R8.2 v1(42.14,52.76)
  L04_PWR1 w0.381: v1(51.95,17.8) 52.59,18.45 53.65,18.47 54.39,18.47 55.22,19.3 55.22,22.35 57.94,25.07 57.94,26.95 57.84,27.05 57.84,27.48 57.94,27.58 57.94,31.37 57.46,31.85 57.46,36.83 53.88,40.41 52.63,40.41 52.28,40.77 49.58,40.77 46.77,43.59 41.15,43.59 39.96,44.78 39.96,48.95 41.18,50.17 41.18,52.07 41.47,52.36 41.73,52.36 v1(42.14,52.76)
  L05_PWR2 w0.178: v1(50.01,17.34) 50.47,17.8 v1(51.95,17.8)
  BOTTOM w0.203: C134.2 50.01,17.22 50.01,17.23 ; 50.01,17.23 C133.2 ; 50.01,17.23 v1(50.01,17.34)
VREF_1.24V: length 3.3
  TOP w0.14: D1.4 60.48,24.05 60.23,24.3 C54.1 R71.1 61.21,24.74 61.21,25.62 R68.1
VRTC: length 9.1
  TOP w0.114: U1.B5 30.42,50.35 28.72,50.35 28.65,50.41
  TOP w0.203: v1(27.25,50.28) 27.38,50.41 28.65,50.41
  L03_SIG1 w0.381: v1(27.25,50.28) 27.25,48.04 27.48,47.81 v1(27.48,46.63)
  BOTTOM w0.381: R98.1 v1(27.48,46.63) ; v1(27.25,50.28) 26.83,50.7 C73.1
WL_DM388_BT_EN: length 11.9
  TOP w0.14: v1(45.04,60.35) 46.13,59.26 46.13,57.76 47.88,56.02 50.72,56.02 50.84,55.89 MOD1.41
  BOTTOM w0.14: U12.13 44.74,60.05 v1(45.04,60.35)
WL_DM388_MCASP0_ACLKX: length 18.4
  TOP w0.14: R13.1 v1(60.87,46.4) ; v1(58.53,33.02) 58.08,33.02 57.83,33.27 R54.2
  BOTTOM w0.14: v1(58.53,33.02) 58.98,33.47 58.98,39.58 57.99,40.56 57.99,42.51 57.99,42.52 57.99,45.19 57.99,45.2 57.99,45.31 59.08,46.4 v1(60.87,46.4)
WL_DM388_MCASP0_AFSX: length 18.7
  TOP w0.14: v1(58.27,37.27) 57.95,36.95 57.88,36.95 57.33,36.4 57.33,36.37 57.28,36.32 57.28,35.46 57.33,35.41 57.33,35.38 R47.2 ; MOD1.58 v1(59.75,49)
  L06_SIG2 w0.119: v1(58.27,37.27) 58.27,37.72 57.43,38.56 57.43,46.14 58.14,46.85 58.14,48.54 57.93,48.75 57.93,49.18 58.24,49.48 59.27,49.48 v1(59.75,49)
WL_DM388_MCASP0_AXR0: length 15.6
  TOP w0.14: MOD1.56 v1(58.35,49) ; R39.2 57.83,36.48 58.05,36.7 v1(58.5,36.7)
  L06_SIG2 w0.119: v1(58.5,36.7) 59.01,37.21 59.01,39.17 57.7,40.47 57.7,41.7 57.7,46.03 58.41,46.74 58.41,48.94 v1(58.35,49)
WL_DM388_MCASP0_AXR1: length 20.8
  TOP w0.14: MOD1.57 v1(59.05,48.34)
  BOTTOM w0.14: R87.2 49.98,59.74 50.32,59.4 50.32,52.48 53.14,49.66 58.91,49.66 59.05,49.52 v1(59.05,48.34)
WL_DM388_MMC0_CLK: length 22.3
  TOP w0.14: U3.1 62.7,40.17 62.38,39.85 v1(62.36,39.85)
  L03_SIG1 w0.119: v1(62.36,39.85) 62.67,40.17 62.67,40.49 64.72,42.55 67.29,42.55 67.69,42.95 67.69,43.59 66.17,45.11 66.17,46.66 66.45,46.94 66.45,48.15 66.3,48.3 v1(66.3,48.74)
  BOTTOM w0.14: v1(66.3,48.74) 66.3,49.58 63.4,52.48 63.4,54.48 64.04,55.12 R89.1
WL_DM388_MMC0_CMD: length 15.1
  TOP w0.14: U3.3 64.58,41.64 66.76,43.82 v1(66.76,46.36)
  BOTTOM w0.14: R93.1 64.07,52.44 66.76,49.76 v1(66.76,46.36)
WL_DM388_MMC0_DAT0: length 18.1
  TOP w0.14: v1(65.84,47.4) 66.16,47.08 66.16,43.68 64.62,42.14 U3.4
  BOTTOM w0.14: v1(65.84,47.4) 65.84,49.43 62.96,52.31 62.96,55.82 63.96,56.82 RA5.5
WL_DM388_MMC0_DAT1: length 18.1
  TOP w0.14: v1(65.66,46.41) 65.66,43.77 64.54,42.64 U3.5
  BOTTOM w0.14: v1(65.66,46.41) 65.31,46.76 65.31,49.35 62.72,51.94 62.72,56.51 63.53,57.32 RA5.6
WL_DM388_MMC0_DAT2: length 18.5
  TOP w0.14: U3.6 64.56,43.14 65.15,43.74 65.15,47.04 v1(64.8,47.4)
  BOTTOM w0.14: v1(64.8,47.4) 64.8,49.43 61.7,52.53 61.7,55.9 63.62,57.82 RA5.7
WL_DM388_MMC0_DAT3: length 18.1
  TOP w0.14: U3.7 64.38,43.64 64.57,43.83 v1(64.57,46.38)
  BOTTOM w0.14: v1(64.57,46.38) 64.16,46.79 64.16,49.65 61.4,52.41 61.4,56.02 63.71,58.32 RA5.8
WL_DM388_UART2_CTSN: length 8
  TOP w0.14: MOD1.50 v1(54.15,49) ; U2.10 v1(54.18,43)
  BOTTOM w0.14: v1(54.15,49) 54.47,48.68 54.47,43.74 54.18,43.45 v1(54.18,43)
WL_DM388_UART2_RTSN: length 8.6
  TOP w0.14: MOD1.51 54.85,48.48 55.81,47.52 55.81,44.4 55.41,44 U2.12
WL_DM388_UART2_RXD: length 9
  TOP w0.14: MOD1.52 55.55,48.44 56.14,47.85 56.14,44.3 55.34,43.5 U2.11
WL_DM388_UART2_TXD: length 7.7
  TOP w0.14: U2.13 v1(55.12,44.5) ; MOD1.53 v1(56.25,48.34)
  BOTTOM w0.14: v1(55.12,44.5) 56.25,45.63 v1(56.25,48.34)
WL_DM388_WLAN_CLKOUT: length 33.7
  TOP w0.14: U5.10 60.04,36.28 59.9,36.42 v1(59.9,36.51) ; MOD1.36 v1(51.43,59.39)
  L06_SIG2 w0.119: v1(51.43,59.39) 50.4,58.37 50.4,47.59 51.26,46.74 56.17,46.74 57.11,45.8 57.11,37.51 58.37,36.25 59.19,36.25 59.45,36.51 v1(59.9,36.51)
WL_DM388_WLAN_EN: length 13.1
  TOP w0.14: v1(45.85,60.78) 45.85,60.24 46.64,59.46 46.64,57.81 48.04,56.41 51.16,56.41 51.34,56.59 MOD1.40
  BOTTOM w0.14: v1(45.85,60.78) 44.73,60.78 44.24,60.29 U12.12
WL_DM388_WLAN_IRQ: length 27.3
  TOP w0.14: MOD1.14 v1(65.89,59.39)
  BOTTOM w0.14: v1(65.89,59.39) 65.89,59.87 64.29,61.47 48.38,61.47 48.26,61.35 48.26,60.8 ; 48.26,60.8 47.67,60.8 46.97,61.49 43.9,61.49 43.24,60.83 U12.10 ; 48.26,60.8 R86.2
XTAL_GND1: length 10.5
  TOP w0.102: 53.27,8.27 52.76,8.78 52.76,9.56 U7.G30
  TOP w0.127: 53.27,8.27 53.81,7.73
  TOP w0.178: 56.69,6.59 Y2.2
  TOP w0.203: C59.1 56.16,6.11 Y2.2 ; C59.1 54.84,6.11 53.81,7.14 53.81,7.73 ; C59.1 55.27,5.12 C62.1 ; 56.69,6.59 57.36,5.92 57.86,5.92 58.69,5.09 Y2.4
XTAL_GND2: length 11.1
  TOP w0.102: 48.38,7.98 47.2,9.16 47.2,9.56 U7.U30
  TOP w0.127: 48.38,7.98 48.57,7.79 48.57,5.76 48.05,5.25 C60.1
  TOP w0.254: Y3.4 48.57,2.12 48.29,2.12 46.69,3.72 46.49,3.72 Y3.2
  TOP w0.381: C60.1 C61.2 47.13,4.55 46.43,3.85 Y3.2
N11812612: length 2
  BOTTOM w0.14: C98.2 28.38,21.51 R107.2 R108.2
N11838777: length 6.1
  TOP w0.102: v1(44.8,19.38) 44.98,19.55 U7.AB10
  BOTTOM w0.102: 41.18,19.97 41.18,19.5 41.46,19.22 42.78,19.22 43.21,18.8 43.97,18.8 44.55,19.38 v1(44.8,19.38)
  BOTTOM w0.14: C111.2 40.53,20.61 41.18,19.97
N11838793: length 4.2
  TOP w0.102: U7.Y24 45.98,12.74 46.45,12.27 v1(46.45,12.21)
  BOTTOM w0.102: v1(46.45,12.21) 46.09,11.85 46.09,11.47 46.08,11.45 46.08,10.16 46.85,9.38 C179.2
N11838802: length 4.8
  TOP w0.102: U7.U9 47.48,20.76 47.52,20.8 v1(47.52,20.85)
  BOTTOM w0.102: v1(47.52,20.85) 47.95,20.85 48.52,21.41 48.52,23.47 49.17,24.12 C99.2
N11838814: length 2.6
  TOP w0.102: v1(48.41,13.66) 48.23,13.84 U7.T22
  BOTTOM w0.102: v1(48.41,13.66) 48.68,13.39 49.2,13.39 49.51,13.08 49.51,12.79 49.84,12.46 C175.2
N11846918: length 2
  TOP w0.102: U7.K20 51.49,14.84 v1(51.51,14.86)
  BOTTOM w0.102: C161.2 52.63,14.2 51.97,14.86 v1(51.51,14.86)
N11847334: length 2
  TOP w0.203: 32.05,47.33 U1.D1 U1.D2 U1.E2
N11848351: length 1.5
  TOP w0.203: U1.H2 U1.H1 34.65,47.25
N11848810: length 4.3
  TOP w0.102: U1.K7 U1.K8
  TOP w0.14: 37.17,55.75 37.17,54.29 35.95,53.06 U1.K8
N11883885: length 13.6
  TOP w0.102: U7.AK6 40.7,21.56 39.43,21.56 39.2,21.79 38.94,21.79
  TOP w0.14: v1(33.18,26.29) 33.18,27.04 33.02,27.19 RA2.4 ; 38.94,21.79 38.64,21.79 38.59,21.75 v1(38.14,21.75)
  L06_SIG2 w0.119: v1(38.14,21.75) 37.84,22.05 37.84,24.91 36.92,25.83 36.29,25.83 36.13,25.99 34.3,25.99 34,26.29 v1(33.18,26.29)
N11883897: length 14.5
  TOP w0.102: v1(41.94,21.8) 41.94,21.74 41.54,21.34 U7.AJ7
  TOP w0.14: RA2.3 32.41,26.54 32.63,26.76 v1(32.67,26.76)
  L06_SIG2 w0.102: 38.94,21.74 39.2,21.49 41.64,21.49 v1(41.94,21.8)
  L06_SIG2 w0.119: 38.94,21.74 38.36,22.33 38.36,24.78 37.02,26.11 36.62,26.11 36.39,26.11 36.25,26.26 34.73,26.26 34.32,26.67 33.38,26.67 33.29,26.76 v1(32.67,26.76)
N11883909: length 13.1
  TOP w0.102: v1(37.5,21.68) 37.84,21.34 38.39,21.34 38.52,21.46 39.2,21.46 39.32,21.34 U7.AK7
  TOP w0.14: RA2.2 32.46,26.04 v1(32.54,26.12)
  L06_SIG2 w0.119: v1(37.5,21.68) 37.5,22.12 37.57,22.19 37.57,24.69 36.7,25.56 36.17,25.56 36.02,25.71 34.19,25.71 33.96,25.95 33.38,25.95 33.24,25.81 32.86,25.81 v1(32.54,26.12)
N11883921: length 16.6
  TOP w0.102: U7.AE4 43.21,22.84 v1(42.95,22.58) ; 31.98,23.75 31.98,23.69 v1(32.31,23.35)
  TOP w0.14: RA2.1 31.98,23.75
  L03_SIG1 w0.102: 38.94,21.81 39.43,21.32 43.2,21.32 43.46,21.59 43.46,22.06 v1(42.95,22.58)
  L03_SIG1 w0.119: v1(32.31,23.35) 32.7,22.96 32.97,22.96 32.97,22.96 35.01,22.96 35.3,22.66 35.3,22.32 35.83,21.79 37.07,21.79 37.09,21.82 37.11,21.82 37.11,21.82 37.11,21.84 37.44,22.17 38.58,22.17 38.94,21.81
N11883933: length 11.7
  TOP w0.102: U7.AK8 40.98,20.92 40.76,21.13 39.14,21.13 39.09,21.18 38.52,21.18 38.48,21.14 37.75,21.14 37.68,21.21 36.86,21.21
  TOP w0.14: RA3.4 35.67,27.05 35.89,27.05 37.07,25.87 37.07,23.79 36.27,22.98 36.27,21.77 36.71,21.33 36.74,21.33 36.86,21.21
N11883945: length 12.5
  TOP w0.102: v1(41.56,20.38) 41.48,20.46 U7.AJ8
  TOP w0.14: v1(35.84,22.48) 35.84,23.97 36.69,24.82 36.69,25.74 35.89,26.54 RA3.3
  L06_SIG2 w0.102: v1(35.84,22.48) 36.15,22.17 36.27,22.17 36.35,22.09 36.35,21.79 36.35,21.79 36.35,21.51 37.16,20.7 40.62,20.7 40.94,20.38 v1(41.56,20.38)
N11883957: length 13.7
  TOP w0.102: U7.AH8 41.98,20.55 42.13,20.4 v1(42.13,20.34)
  TOP w0.14: RA3.2 35.89,26.04 36.22,25.71 v1(36.22,25.15)
  L06_SIG2 w0.102: v1(42.13,20.34) 42.13,20.77 41.89,21.01 37.19,21.01 36.63,21.57 36.63,22.31 36.44,22.49 36.44,22.64 35.61,23.47 35.61,24.23 35.12,24.72 35.12,25.06 35.46,25.4 35.95,25.4 36.2,25.15 v1(36.22,25.15)
N11883969: length 12.3
  TOP w0.102: v1(42.76,20.34) 42.72,20.34 42.48,20.59 U7.AG8
  TOP w0.14: RA3.1 v1(35.54,24.89)
  L06_SIG2 w0.102: v1(42.76,20.34) 42.46,20.64 42.46,20.82 42.04,21.24 37.29,21.24 36.83,21.69 36.83,21.94 37.27,22.38 37.27,23 37.01,23.27 36.2,23.27 35.88,23.58 35.88,24.61 35.59,24.89 v1(35.54,24.89)
N12895522: length 8.6
  TOP w0.102: 53.25,7.79 53.24,7.8 53.24,7.85 52.82,8.27 52.78,8.27 52.48,8.57 U7.G31
  TOP w0.14: Y2.3 56.64,4.43 56.32,4.11 C62.2 55.26,4.11 54.64,4.74 54.64,5.71 53.25,7.09 53.25,7.79
N12895682: length 10.6
  TOP w0.102: U7.V30 46.98,8.93 47.65,8.26 47.65,8.13 47.99,7.79
  TOP w0.14: 47.99,7.79 48.15,7.63 48.15,6.21 47.81,5.87 46.77,5.87 46.15,5.25 C61.1 46.15,5.17 45.68,4.7 45.66,4.7 45.46,4.5 45.46,2.54 45.81,2.19 Y3.3
N12895686: length 6.5
  TOP w0.102: U7.U31 49.01,7.81 49.01,7.79
  TOP w0.14: 49.01,7.79 49.03,7.77 C60.2 49.03,5.2 48.5,4.67 48.5,3.91 Y3.1
N12909578: length 6.5
  TOP w0.102: 33.73,54.4 33.68,54.35 33.68,52.31 U1.F7
  TOP w0.14: 33.73,54.4 33.94,54.61 33.94,55.48 C11.2 34.21,56.28 34.32,56.39 34.73,56.39 34.86,56.52 Y1.1
N12909638: length 6
  TOP w0.102: U1.F8 33.35,54.4
  TOP w0.14: 33.35,54.4 33.35,54.53 33.56,54.74 33.56,55.48 C10.2 33.3,55.77 33.3,56.26 33.18,56.39 32.54,56.39 32.36,56.57 Y1.2
N12910002: length 1.3
  TOP w0.14: U1.G8 34.22,52.85 v1(34.22,53.15)
  BOTTOM w0.14: C71.2 33.89,53.15 v1(34.22,53.15)
N12911225: length 5.6
  TOP w0.102: 39.55,47.41 39.12,47.83 39.12,48.03 38.43,48.73 U1.N2
  TOP w0.14: 39.55,47.41 39.98,47.41 40.46,46.92 v2(41.87,46.92)
  BOTTOM w0.14: R97.2 42.06,46.73 v2(41.87,46.92)
N12911351: length 9.6
  TOP w0.102: U1.J5 v1(35.09,50.47)
  BOTTOM w0.102: 30.3,46.3 32.01,48.01 32.01,49.38 32.44,49.81 34.43,49.81 v1(35.09,50.47)
  BOTTOM w0.14: 30.3,46.3 29.98,45.97 R98.2
N12969077: length 3.2
  TOP w0.102: U7.M24 49.98,12.76 50.46,12.27 50.46,12.12 v1(50.5,12.07)
  BOTTOM w0.102: C174.2 51.9,12.55 51.41,12.06 50.52,12.06 v1(50.5,12.07)
N12971691: length 5.2
  TOP w0.102: 29.43,48.64 29.84,49.05 30.42,49.05 U1.B3
  TOP w0.14: R12.1 27.77,47.56 28.86,48.64 29.43,48.64
N12971710: length 1.7
  TOP w0.102: U1.C5 v1(31.61,50.47)
  BOTTOM w0.102: C75.1 31.13,49.76 31.4,50.03 31.4,50.26 v1(31.61,50.47)
N12972021: length 6.2
  TOP w0.102: v1(28.54,49.21) 28.75,49.21 29.25,49.71 29.96,49.71 30.43,49.71 30.45,49.73 30.45,49.73 U1.B4
  BOTTOM w0.203: C75.2 29.77,49.66 28.99,49.66 v1(28.54,49.21) 28.47,49.28 R141.1 27.84,49.29 C190.2
N12972241: length 19.6
  TOP w0.203: Q2.3 12.82,47.86 v1(12.82,47.28) ; U1.A3 29.59,49.38 v2(29.3,49.08)
  L06_SIG2 w0.203: v2(29.3,49.08) 28.32,48.11 27.82,48.11 27.23,48.69 14.24,48.69 v1(12.82,47.28)
N12972253: length 7.7
  TOP w0.14: 29.53,51.51 29.53,51.5
  TOP w0.203: U1.A6 29.93,51.5 29.53,51.5 ; v1(24.41,50.17) 24.27,50.31 Q1.3 ; v2(29.17,51.87) 29.53,51.51
  L03_SIG1 w0.203: v2(29.17,51.87) 26.12,51.87 v1(24.41,50.17)
N12973009: length 2.2
  TOP w0.102: U1.A2 29.83,48.73 29.66,48.55 29.66,48.55 29.53,48.42 v2(29.3,48.19)
  BOTTOM w0.102: v2(29.3,48.19) 29.24,48.13 28.81,48.13 C77.1
N12973023: length 5.7
  TOP w0.203: v1(26.64,48.25) 26.64,48.74 27.69,49.78 28.49,49.78 28.73,50.03 U1.A4
  BOTTOM w0.14: C77.2 26.79,47.65 26.64,47.8 v1(26.64,48.25)
N12985066: length 2.2
  TOP w0.14: R85.2 38.11,1.18 38.58,1.65 38.97,1.65 39.69,2.38 39.69,2.45
N12985136: length 1.5
  TOP w0.14: U10.3 38.34,4.92 38.27,4.99 R82.1
N12993482: length 3.5
  TOP w0.14: U8.L8 v1(25.91,6.79)
  BOTTOM w0.102: R132.2 26.93,7.81 v1(25.91,6.79)
N14066974: length 5.1
  TOP w0.14: v1(24.64,34.85) 24.87,34.62 26.93,34.62 27.17,34.87 Q3.3
  BOTTOM w0.14: v1(24.64,34.85) 24.64,33.96 24.78,33.82 U14.11
N14067031: length 3.2
  TOP w0.14: v1(26.51,35.05) 25.39,35.05 24.86,35.58 Q4.3
  BOTTOM w0.14: v1(26.51,35.05) 26.51,34.74 26.2,34.43 U14.14
N14067125: length 3.5
  BOTTOM w0.203: 25.8,34.93 U14.13
  BOTTOM w0.305: v1(25.88,36) 25.88,35.01 25.8,34.93
  BOTTOM w0.508: C84.2 v1(26.45,35.97) 25.9,35.97 v1(25.88,36)
N14068093: length 1.6
  BOTTOM w0.14: U14.18 28.11,32.32 28.26,32.17 R99.1
N14068298: length 4.7
  TOP w0.14: R61.1 v1(22.03,32.61)
  BOTTOM w0.14: U14.8 23.54,32.32 23.33,32.53 23.33,32.53 23.24,32.61 v1(22.03,32.61) ; v1(22.03,32.61) 21.96,32.55 R100.2 ; v1(22.03,32.61) 21.86,32.78 C85.1
N14068467: length 2.6
  BOTTOM w0.14: C86.2 R100.1 23.36,31.52 U14.6
N14068656: length 1.9
  BOTTOM w0.14: U14.19 28.1,31.92 R102.2
N14068754: length 1.6
  BOTTOM w0.14: C84.1 27.21,34.06 26.97,33.82 U14.15
N14086942: length 1.3
  TOP w0.14: U3.10 62.7,45.82 62.69,45.83 R14.2
N14162633: length 1.6
  TOP w0.14: C57.1 69.31,9.46 69.21,9.56 U9.4
N14387261: length 2
  TOP w0.14: R10.2 49.9,46.91 49.8,46.81 U2.2
N14387269: length 3.2
  TOP w0.14: U2.3 49.1,45 48.84,45.27 R11.1
